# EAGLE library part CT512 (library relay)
ULTRA SMALL AUTOMOTIVE RELAY NAiS Twin type (10 terminals) en_ds_61205_0000.pdf
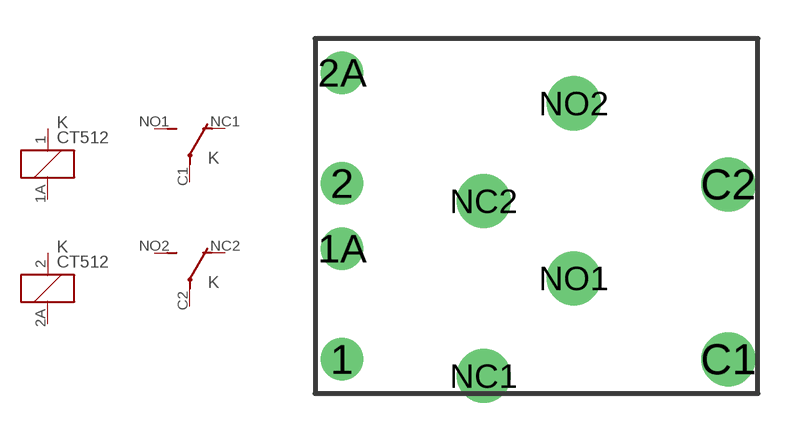
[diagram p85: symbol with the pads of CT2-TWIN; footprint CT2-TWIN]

Designator prefix K; gates A=K B=K A1=U B1=U

## CT512 (OC_FARNELL: unknown; OC_NEWARK: unknown)  [CT2-TWIN]
1  A:1  pas
1A  A:2  pas
2  B:1  pas
2A  B:2  pas
C1  A1:P  pas
C2  B1:P  pas
NC1  A1:O  pas
NC2  B1:O  pas
NO1  A1:S  pas
NO2  B1:S  pas

## Footprint CT2-TWIN (pad centres in mm)
ULTRA SMALL AUTOMOTIVE RELAY NAiS Twin type (10 terminals) Source: http://www.mew-europe.com/.. en_ds_61205_0000.pdf
drill 1.1 round: 1 -7.45,-5.57; 1A -7.45,-1.27; 2 -7.45,1.27; 2A -7.45,5.57
drill 1.4 round: C1 7.55,-5.57; C2 7.55,1.23; NC1 -1.95,-6.22; NC2 -1.95,0.58; NO1 1.55,-2.42; NO2 1.55,4.38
